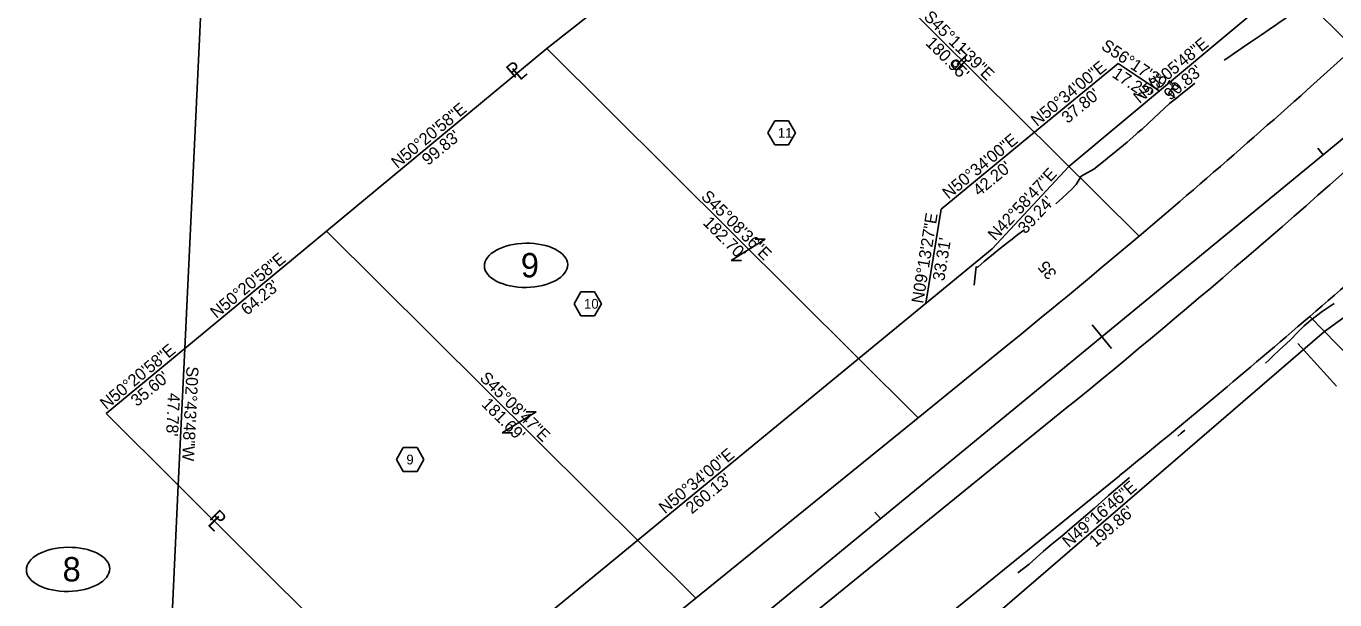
# Model space of a CAD drawing. Extents: x 1145508 to 2262867, y -3126236 to 2021677.
# Drawn here: x 1146747.3 to 1147204, y 2017009.2 to 2017209.5 of the extents above; entities that cross this region are included whole.
import ezdxf

# ---------------------------------------------------------------- set-up
doc = ezdxf.new("R2010")
doc.units = 0
for name, color, linetype in [('Default', 7, 'Continuous'), ('DSN_RDWY_Alignment Annotation', 7, 'Continuous'), ('DSN_RDWY_Const Limits', 7, 'Continuous'), ('DSN_ROW_Annotation', 7, 'Continuous'), ('DSN_ROW_Esmnt', 7, 'Continuous'), ('DSN_ROW_Line', 7, 'Continuous'), ('DSN_ROW_Line-Annotation', 7, 'Continuous'), ('DSN_ROW_Prop-Line', 7, 'Continuous'), ('DSN_ROW_Prop-Line-Annotation', 7, 'Continuous'), ('E_Const Align', 7, 'Continuous'), ('EX_ROW', 7, 'Continuous'), ('EX_ROW_ANNOT', 7, 'Continuous'), ('EX_SECTION', 7, 'Continuous'), ('EX_SIGN', 7, 'Continuous'), ('EX_SUBDIV_ANNOT', 7, 'Continuous')]:
    doc.layers.add(name, color=color, linetype=linetype)

msp = doc.modelspace()

# ---------------------------------------------------------------- linework, layer by layer
at = {"layer": 'Default'}
msp.add_line((1147109.89, 2017075.82), (1146880.36, 2016889.44), dxfattribs=at)
msp.add_arc((1145304.01, 2019299.75), 2864.79, 309.07734, 312.59711, dxfattribs=at)
at = {"layer": 'DSN_RDWY_Alignment Annotation'}
for p, q in [((1147197.98, 2017166.89), (1147199.88, 2017164.57)), ((1147119.25, 2017105.18), (1147126, 2017096.98)), ((1147043.5, 2017039.85), (1147045.41, 2017037.54))]:
    msp.add_line(p, q, dxfattribs=at)
at = {"layer": 'DSN_RDWY_Const Limits'}
for points in [[(1147165.35, 2017197.55), (1147165.93, 2017197.98), (1147170.07, 2017200.82), (1147171.13, 2017201.54), (1147171.61, 2017201.87), (1147174.22, 2017203.65), (1147178.36, 2017206.48), (1147182.5, 2017209.32), (1147183.48, 2017209.98), (1147184.12, 2017210.42), (1147186.65, 2017212.15), (1147190.69, 2017215.11), (1147194.74, 2017218.06), (1147195.69, 2017218.73), (1147196.32, 2017219.18), (1147198.81, 2017220.97), (1147202.85, 2017223.93), (1147206.77, 2017227.04)], [(1147106.61, 2017147.46), (1147108.81, 2017149.36), (1147112.47, 2017152.78), (1147113.4, 2017153.83), (1147113.68, 2017154.14), (1147115.44, 2017157.04), (1147119.87, 2017159.53), (1147123.77, 2017162.66), (1147124.75, 2017163.47), (1147125.23, 2017163.88), (1147127.61, 2017165.86), (1147131.55, 2017168.95), (1147134.53, 2017171.62), (1147135.27, 2017172.29), (1147136.22, 2017173.14), (1147136.69, 2017173.56), (1147138.99, 2017175.64), (1147142.61, 2017179.1), (1147146.31, 2017182.48), (1147147.34, 2017183.33), (1147147.73, 2017183.63), (1147148.65, 2017184.36), (1147150.22, 2017185.61), (1147154.13, 2017188.72), (1147155.13, 2017189.52)], [(1147078.13, 2017119.04), (1147078.73, 2017124.54), (1147078.81, 2017125.29), (1147078.83, 2017125.45), (1147079.34, 2017125.38), (1147081.64, 2017127.31), (1147085.48, 2017130.5), (1147086.27, 2017131.12), (1147089.41, 2017133.6), (1147090.57, 2017134.52), (1147090.75, 2017134.66), (1147093.35, 2017136.68), (1147095.69, 2017138.34)], [(1147179.73, 2017091.85), (1147181.04, 2017093.02), (1147181.96, 2017093.91), (1147182.41, 2017094.35), (1147184.64, 2017096.51), (1147188.34, 2017099.88), (1147191.15, 2017102.77), (1147191.85, 2017103.5), (1147192.74, 2017104.41), (1147193.22, 2017104.82), (1147195.57, 2017106.84), (1147199.59, 2017109.82), (1147203.77, 2017112.61)], [(1147149.12, 2017066.38), (1147150.35, 2017067.37), (1147151.65, 2017068.45)], [(1147093.38, 2017018.57), (1147097.3, 2017021.67), (1147101.01, 2017025.03), (1147102.19, 2017026.1), (1147102.21, 2017026.11), (1147104.77, 2017028.33), (1147108.68, 2017031.45), (1147112.46, 2017034.72), (1147113.67, 2017035.76), (1147113.68, 2017035.77), (1147116.25, 2017037.98), (1147120.05, 2017041.23), (1147123.79, 2017044.56), (1147124.94, 2017045.58), (1147125.03, 2017045.66), (1147127.57, 2017047.83), (1147131.4, 2017051.05), (1147132.35, 2017051.92)]]:
    msp.add_lwpolyline(points, dxfattribs=at)
at = {"layer": 'DSN_ROW_Esmnt'}
for p, q in [((1147099.19, 2017172.4), (1147128.39, 2017196.41)), ((1147128.39, 2017196.41), (1147142.71, 2017186.85)), ((1147066.6, 2017145.59), (1147099.19, 2017172.4)), ((1147061.26, 2017112.72), (1147066.6, 2017145.59))]:
    msp.add_line(p, q, dxfattribs=at)
at = {"layer": 'DSN_ROW_Line'}
for p, q in [((1147111.19, 2017160.48), (1147187.77, 2017224.53)), ((1147200.36, 2017102.81), (1147283.43, 2017163.37)), ((1147084.43, 2017131.78), (1147111.19, 2017160.48)), ((1146883.52, 2016966.54), (1147084.43, 2017131.78)), ((1147048.88, 2016972.43), (1147200.36, 2017102.81))]:
    msp.add_line(p, q, dxfattribs=at)
at = {"layer": 'DSN_ROW_Line-Annotation'}
for centre in [(1146921.75, 2017125.97), (1146761.93, 2017019.82)]:
    msp.add_ellipse(centre, major_axis=(14.54, 0.23), ratio=0.529773, dxfattribs=at)
at = {"layer": 'DSN_ROW_Prop-Line'}
for p, q in [((1147083.32, 2017328.61), (1147210.54, 2017201.84)), ((1146929.01, 2017201.62), (1147007.29, 2017263.68)), ((1147007.29, 2017263.68), (1147135.67, 2017136.17)), ((1146852.15, 2017137.92), (1146929.01, 2017201.62)), ((1146929.01, 2017201.62), (1147058.52, 2017072.76)), ((1146802.69, 2017096.93), (1146852.15, 2017137.92)), ((1146852.15, 2017137.92), (1146980.95, 2017009.77)), ((1147327.37, 2016972.93), (1147195.18, 2017108.11)), ((1146775.28, 2017074.21), (1146802.69, 2017096.93))]:
    msp.add_line(p, q, dxfattribs=at)
at = {"layer": 'DSN_ROW_Prop-Line-Annotation'}
for p, q in [((1147005.21, 2017135.06), (1146993.36, 2017127.67)), ((1147001.66, 2017135.06), (1147005.21, 2017135.06)), ((1146993.36, 2017127.67), (1146996.9, 2017127.67)), ((1146925.32, 2017074.82), (1146913.46, 2017067.44)), ((1146921.77, 2017074.82), (1146925.32, 2017074.82)), ((1146913.46, 2017067.44), (1146917.01, 2017067.44))]:
    msp.add_line(p, q, dxfattribs=at)
at = {"layer": 'E_Const Align'}
msp.add_line((1146840, 2016868.61), (1147825.51, 2017679.08), dxfattribs=at)
at = {"layer": 'EX_ROW'}
for p, q in [((1147058.52, 2017072.76), (1147090.98, 2017099.11)), ((1146775.28, 2017074.21), (1146800.42, 2017049.21)), ((1146980.95, 2017009.77), (1147058.52, 2017072.76)), ((1146800.42, 2017049.21), (1146903.38, 2016946.78)), ((1147040.91, 2016981.16), (1147128.8, 2017052.53)), ((1146903.38, 2016946.78), (1146980.95, 2017009.77))]:
    msp.add_line(p, q, dxfattribs=at)
for radius, start, end in [(2834.79, 310.25076, 312.2638), (2894.79, 310.79095, 312.59711), (2834.79, 309.07734, 310.25076), (2894.79, 309.07734, 310.79095)]:
    msp.add_arc((1145304.01, 2019299.75), radius, start, end, dxfattribs=at)
at = {"layer": 'EX_SECTION'}
for p, q in [((1146895.16, 2019036.08), (1146802.69, 2017096.93)), ((1146802.69, 2017096.93), (1146800.42, 2017049.21)), ((1146800.42, 2017049.21), (1146794.02, 2016915.09))]:
    msp.add_line(p, q, dxfattribs=at)
at = {"layer": 'EX_SIGN'}
msp.add_line((1147204.5, 2017083.82), (1147191.03, 2017098.68), dxfattribs=at)
at = {"layer": 'EX_SUBDIV_ANNOT'}
for p, q in [((1147006.11, 2017172.2), (1147008.51, 2017176.36)), ((1147008.51, 2017176.36), (1147013.31, 2017176.36)), ((1147013.31, 2017176.36), (1147015.71, 2017172.2)), ((1147008.51, 2017168.04), (1147006.11, 2017172.2)), ((1147015.71, 2017172.2), (1147013.32, 2017168.04)), ((1147013.32, 2017168.04), (1147008.51, 2017168.04)), ((1146938.48, 2017112.54), (1146940.88, 2017116.7)), ((1146940.88, 2017108.38), (1146938.48, 2017112.54)), ((1146940.88, 2017116.7), (1146945.68, 2017116.7)), ((1146945.68, 2017116.7), (1146948.08, 2017112.54)), ((1146948.08, 2017112.54), (1146945.68, 2017108.38)), ((1146945.68, 2017108.38), (1146940.88, 2017108.38)), ((1146876.5, 2017058.17), (1146878.9, 2017062.33)), ((1146878.9, 2017062.33), (1146883.7, 2017062.33)), ((1146883.7, 2017062.33), (1146886.1, 2017058.17)), ((1146878.9, 2017054.01), (1146876.5, 2017058.17)), ((1146886.1, 2017058.17), (1146883.7, 2017054.01)), ((1146883.7, 2017054.01), (1146878.9, 2017054.01))]:
    msp.add_line(p, q, dxfattribs=at)

# ---------------------------------------------------------------- texts
at = {"layer": 'DSN_RDWY_Alignment Annotation'}
msp.add_text('35', height=4.2, rotation=129.4333, dxfattribs=at).set_placement((1147107.19, 2017123.15))
at = {"layer": 'DSN_ROW_Annotation'}
for s, rotation, p in [('S45°11\'39"E', 315.1941, (1147060.22, 2017212.38)), ("180.95'", 315.1941, (1147060.89, 2017203.25)), ('S56°17\'39"E', 326.2941, (1147122.11, 2017201.68)), ('N50°05\'48"E', 39.9035, (1147135.82, 2017182.25)), ('N50°34\'00"E', 39.4333, (1147100.04, 2017174.26)), ("17.22'", 326.2941, (1147125.94, 2017191.91)), ("99.83'", 39.9035, (1147146.5, 2017183.36)), ("37.80'", 39.4333, (1147110.73, 2017175.28)), ('N50°20\'58"E', 39.6505, (1146876.87, 2017159.58)), ("99.83'", 39.6505, (1146887.56, 2017160.64)), ('N50°34\'00"E', 39.4333, (1147069.15, 2017148.86)), ("42.20'", 39.4333, (1147079.84, 2017149.88)), ('N42°58\'47"E', 47.0202, (1147085.52, 2017134.27)), ('S45°08\'36"E', 315.1434, (1146982.52, 2017149.65)), ("39.24'", 47.0202, (1147095.98, 2017136.69)), ('N09°13\'27"E', 80.7757, (1147060.31, 2017112.46)), ("182.70'", 315.1434, (1146983.18, 2017140.53)), ("33.31'", 80.7757, (1147067.66, 2017120.29)), ('N50°20\'58"E', 39.6505, (1146813.71, 2017107.23)), ("64.23'", 39.6505, (1146824.4, 2017108.3)), ('N50°20\'58"E', 39.6505, (1146775.28, 2017075.38)), ("35.60'", 39.6505, (1146785.97, 2017076.45)), ('S45°08\'47"E', 315.1464, (1146905.3, 2017086.3)), ("181.69'", 315.1464, (1146905.96, 2017077.18)), ('N50°34\'00"E', 39.4333, (1146970.23, 2017039.02)), ("260.13'", 39.4333, (1146979.6, 2017038.96)), ('N49°16\'46"E', 40.7207, (1147111.1, 2017027.18)), ("199.86'", 40.7207, (1147120.47, 2017027.33))]:
    msp.add_text(s, height=4.2, rotation=rotation, dxfattribs=at).set_placement(p)
at = {"layer": 'DSN_ROW_Line-Annotation'}
for s, p in [('9', (1146919.93, 2017121.76)), ('8', (1146760.04, 2017015.61))]:
    msp.add_text(s, height=8.5, dxfattribs=at).set_placement(p)
at = {"layer": 'DSN_ROW_Prop-Line-Annotation'}
for s, rotation, p in [('L', 135.169, (1147076.31, 2017199.02)), ('P', 40.5823, (1146917.5, 2017191)), ('L', 40.5823, (1146919.64, 2017190.3)), ('P', 135.169, (1147075.79, 2017196.84)), ('P', 315.169, (1146810.93, 2017037.6)), ('L', 315.169, (1146810.41, 2017035.42))]:
    msp.add_text(s, height=5, rotation=rotation, dxfattribs=at).set_placement(p)
at = {"layer": 'EX_ROW_ANNOT'}
for s, p in [('S02°43\'48"W', (1146803.3, 2017090.78)), ('S02°43\'48"W', (1146803.3, 2017090.78)), ("47.78'", (1146796.85, 2017081.46)), ("47.78'", (1146796.85, 2017081.46))]:
    msp.add_text(s, height=4.2, rotation=267.27, dxfattribs=at).set_placement(p)
at = {"layer": 'EX_SUBDIV_ANNOT'}
for s, height, p in [('11', 3.418, (1147009.61, 2017170.49)), ('10', 3.418, (1146941.98, 2017110.83)), ('9', 3.42, (1146880, 2017056.46))]:
    msp.add_text(s, height=height, dxfattribs=at).set_placement(p)

doc.saveas('drawing.dxf')
